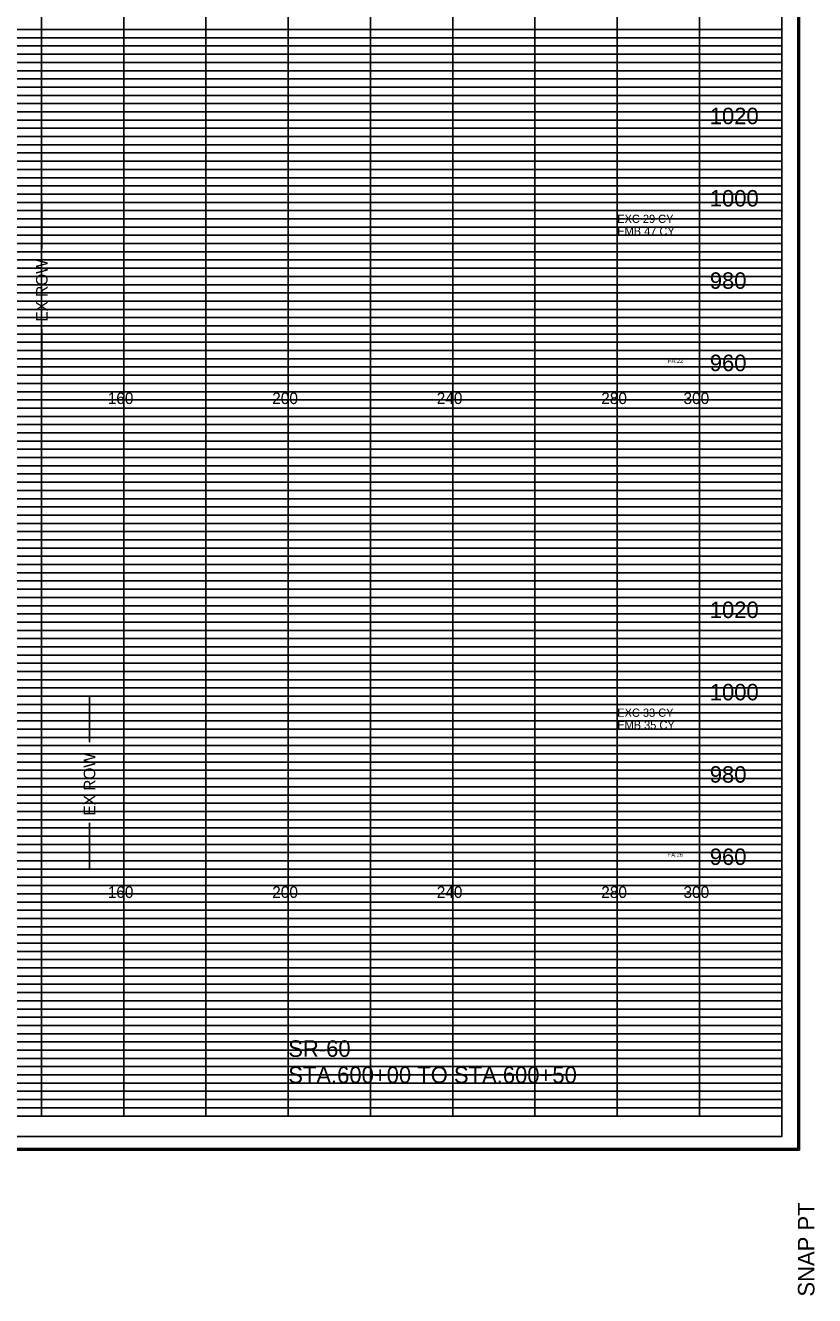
# Model space of a CAD drawing. Extents: x 2313580 to 2322968, y 282099 to 303247.
# Drawn here: x 2317337.4 to 2317529.3, y 287544 to 287852.7 of the extents above; entities that cross this region are included whole.
import ezdxf

# ---------------------------------------------------------------- set-up
doc = ezdxf.new("R2010")
doc.units = 0
for name, color, linetype in [('DESIGN - EARTHWORK - Excavation Limit Lines', 7, 'Continuous'), ('DESIGN - SHEET - Corner Text', 7, 'Continuous'), ('DESIGN - SHEET - Light Grid', 7, 'Continuous'), ('DESIGN - SHEET - Linework', 7, 'Continuous'), ('DESIGN - SHEET - Plot Shape', 7, 'Continuous'), ('DESIGN - TYPICAL - Text', 7, 'Continuous'), ('Prop_ CL text', 7, 'Continuous'), ('SURVEY - PROPERTY - ROW Lines Text', 7, 'Continuous')]:
    doc.layers.add(name, color=color, linetype=linetype)

msp = doc.modelspace()

# ---------------------------------------------------------------- linework, layer by layer
at = {"layer": 'DESIGN - SHEET - Light Grid'}
for p, q in [((2317201.28, 287851.67), (2317361.28, 287851.67)), ((2317361.28, 287851.67), (2317521.28, 287851.67)), ((2317201.28, 287849.67), (2317361.28, 287849.67)), ((2317361.28, 287849.67), (2317521.28, 287849.67)), ((2317201.28, 287845.67), (2317361.28, 287845.67)), ((2317361.28, 287845.67), (2317521.28, 287845.67)), ((2317201.28, 287843.67), (2317361.28, 287843.67)), ((2317201.28, 287841.67), (2317361.28, 287841.67)), ((2317361.28, 287843.67), (2317521.28, 287843.67)), ((2317361.28, 287841.67), (2317521.28, 287841.67)), ((2317201.28, 287839.67), (2317361.28, 287839.67)), ((2317361.28, 287839.67), (2317521.28, 287839.67)), ((2317201.28, 287837.67), (2317361.28, 287837.67)), ((2317201.28, 287835.67), (2317361.28, 287835.67)), ((2317361.28, 287837.67), (2317521.28, 287837.67)), ((2317361.28, 287835.67), (2317521.28, 287835.67)), ((2317201.28, 287833.67), (2317361.28, 287833.67)), ((2317201.28, 287831.67), (2317361.28, 287831.67)), ((2317361.28, 287833.67), (2317521.28, 287833.67)), ((2317361.28, 287831.67), (2317521.28, 287831.67)), ((2317201.28, 287829.67), (2317361.28, 287829.67)), ((2317361.28, 287829.67), (2317521.28, 287829.67)), ((2317201.28, 287825.67), (2317361.28, 287825.67)), ((2317361.28, 287825.67), (2317521.28, 287825.67)), ((2317201.28, 287823.67), (2317361.28, 287823.67)), ((2317361.28, 287823.67), (2317521.28, 287823.67)), ((2317201.28, 287821.67), (2317361.28, 287821.67)), ((2317201.28, 287819.67), (2317361.28, 287819.67)), ((2317361.28, 287821.67), (2317521.28, 287821.67)), ((2317361.28, 287819.67), (2317521.28, 287819.67)), ((2317201.28, 287817.67), (2317361.28, 287817.67)), ((2317361.28, 287817.67), (2317521.28, 287817.67)), ((2317201.28, 287815.67), (2317361.28, 287815.67)), ((2317201.28, 287813.67), (2317361.28, 287813.67)), ((2317361.28, 287815.67), (2317521.28, 287815.67)), ((2317361.28, 287813.67), (2317521.28, 287813.67)), ((2317201.28, 287811.67), (2317361.28, 287811.67)), ((2317361.28, 287811.67), (2317521.28, 287811.67)), ((2317201.28, 287809.67), (2317361.28, 287809.67)), ((2317361.28, 287809.67), (2317521.28, 287809.67)), ((2317201.28, 287805.67), (2317361.28, 287805.67)), ((2317361.28, 287805.67), (2317521.28, 287805.67)), ((2317201.28, 287803.67), (2317361.28, 287803.67)), ((2317201.28, 287801.67), (2317361.28, 287801.67)), ((2317361.28, 287803.67), (2317521.28, 287803.67)), ((2317361.28, 287801.67), (2317521.28, 287801.67)), ((2317201.28, 287799.67), (2317361.28, 287799.67)), ((2317201.28, 287797.67), (2317361.28, 287797.67)), ((2317361.28, 287799.67), (2317521.28, 287799.67)), ((2317361.28, 287797.67), (2317521.28, 287797.67)), ((2317201.28, 287795.67), (2317361.28, 287795.67)), ((2317361.28, 287795.67), (2317521.28, 287795.67)), ((2317201.28, 287793.67), (2317361.28, 287793.67)), ((2317201.28, 287791.67), (2317361.28, 287791.67)), ((2317361.28, 287793.67), (2317521.28, 287793.67)), ((2317361.28, 287791.67), (2317521.28, 287791.67)), ((2317201.28, 287789.67), (2317361.28, 287789.67)), ((2317361.28, 287789.67), (2317521.28, 287789.67)), ((2317201.28, 287785.67), (2317361.28, 287785.67)), ((2317361.28, 287785.67), (2317521.28, 287785.67)), ((2317201.28, 287783.67), (2317361.28, 287783.67)), ((2317361.28, 287783.67), (2317521.28, 287783.67)), ((2317201.28, 287781.67), (2317361.28, 287781.67)), ((2317201.28, 287779.67), (2317361.28, 287779.67)), ((2317361.28, 287781.67), (2317521.28, 287781.67)), ((2317361.28, 287779.67), (2317521.28, 287779.67)), ((2317201.28, 287777.67), (2317361.28, 287777.67)), ((2317361.28, 287777.67), (2317521.28, 287777.67)), ((2317201.28, 287775.67), (2317361.28, 287775.67)), ((2317201.28, 287773.67), (2317361.28, 287773.67)), ((2317361.28, 287775.67), (2317521.28, 287775.67)), ((2317361.28, 287773.67), (2317521.28, 287773.67)), ((2317201.28, 287771.67), (2317361.28, 287771.67)), ((2317361.28, 287771.67), (2317521.28, 287771.67)), ((2317201.28, 287769.67), (2317361.28, 287769.67)), ((2317361.28, 287769.67), (2317521.28, 287769.67)), ((2317201.28, 287765.67), (2317361.28, 287765.67)), ((2317201.28, 287763.67), (2317361.28, 287763.67)), ((2317361.28, 287765.67), (2317521.28, 287765.67)), ((2317361.28, 287763.67), (2317521.28, 287763.67)), ((2317201.28, 287761.67), (2317361.28, 287761.67)), ((2317361.28, 287761.67), (2317521.28, 287761.67)), ((2317201.28, 287759.67), (2317361.28, 287759.67)), ((2317201.28, 287757.67), (2317361.28, 287757.67)), ((2317361.28, 287759.67), (2317521.28, 287759.67)), ((2317361.28, 287757.67), (2317521.28, 287757.67)), ((2317201.28, 287755.67), (2317361.28, 287755.67)), ((2317361.28, 287755.67), (2317521.28, 287755.67)), ((2317201.28, 287753.67), (2317361.28, 287753.67)), ((2317201.28, 287751.67), (2317361.28, 287751.67)), ((2317361.28, 287753.67), (2317521.28, 287753.67)), ((2317361.28, 287751.67), (2317521.28, 287751.67)), ((2317201.28, 287749.67), (2317361.28, 287749.67)), ((2317361.28, 287749.67), (2317521.28, 287749.67)), ((2317201.28, 287745.67), (2317361.28, 287745.67)), ((2317361.28, 287745.67), (2317521.28, 287745.67)), ((2317201.28, 287743.67), (2317361.28, 287743.67)), ((2317361.28, 287743.67), (2317521.28, 287743.67)), ((2317201.28, 287741.67), (2317361.28, 287741.67)), ((2317201.28, 287739.67), (2317361.28, 287739.67)), ((2317361.28, 287741.67), (2317521.28, 287741.67)), ((2317361.28, 287739.67), (2317521.28, 287739.67)), ((2317201.28, 287737.67), (2317361.28, 287737.67)), ((2317361.28, 287737.67), (2317521.28, 287737.67)), ((2317201.28, 287735.67), (2317361.28, 287735.67)), ((2317201.28, 287733.67), (2317361.28, 287733.67)), ((2317361.28, 287735.67), (2317521.28, 287735.67)), ((2317361.28, 287733.67), (2317521.28, 287733.67)), ((2317201.28, 287731.67), (2317361.28, 287731.67)), ((2317361.28, 287731.67), (2317521.28, 287731.67)), ((2317201.28, 287729.67), (2317361.28, 287729.67)), ((2317361.28, 287729.67), (2317521.28, 287729.67)), ((2317201.28, 287725.67), (2317361.28, 287725.67)), ((2317201.28, 287723.67), (2317361.28, 287723.67)), ((2317361.28, 287725.67), (2317521.28, 287725.67)), ((2317361.28, 287723.67), (2317521.28, 287723.67)), ((2317201.28, 287721.67), (2317361.28, 287721.67)), ((2317361.28, 287721.67), (2317521.28, 287721.67)), ((2317201.28, 287719.67), (2317361.28, 287719.67)), ((2317201.28, 287717.67), (2317361.28, 287717.67)), ((2317361.28, 287719.67), (2317521.28, 287719.67)), ((2317361.28, 287717.67), (2317521.28, 287717.67)), ((2317201.28, 287715.67), (2317361.28, 287715.67)), ((2317361.28, 287715.67), (2317521.28, 287715.67)), ((2317201.28, 287713.67), (2317361.28, 287713.67)), ((2317201.28, 287711.67), (2317361.28, 287711.67)), ((2317361.28, 287713.67), (2317521.28, 287713.67)), ((2317361.28, 287711.67), (2317521.28, 287711.67)), ((2317201.28, 287709.67), (2317361.28, 287709.67)), ((2317361.28, 287709.67), (2317521.28, 287709.67)), ((2317201.28, 287705.67), (2317361.28, 287705.67)), ((2317361.28, 287705.67), (2317521.28, 287705.67)), ((2317201.28, 287703.67), (2317361.28, 287703.67)), ((2317361.28, 287703.67), (2317521.28, 287703.67)), ((2317201.28, 287701.67), (2317361.28, 287701.67)), ((2317201.28, 287699.67), (2317361.28, 287699.67)), ((2317361.28, 287701.67), (2317521.28, 287701.67)), ((2317361.28, 287699.67), (2317521.28, 287699.67)), ((2317201.28, 287697.67), (2317361.28, 287697.67)), ((2317361.28, 287697.67), (2317521.28, 287697.67)), ((2317201.28, 287695.67), (2317361.28, 287695.67)), ((2317201.28, 287693.67), (2317361.28, 287693.67)), ((2317361.28, 287695.67), (2317521.28, 287695.67)), ((2317361.28, 287693.67), (2317521.28, 287693.67)), ((2317201.28, 287691.67), (2317361.28, 287691.67)), ((2317201.28, 287689.67), (2317361.28, 287689.67)), ((2317361.28, 287691.67), (2317521.28, 287691.67)), ((2317361.28, 287689.67), (2317521.28, 287689.67)), ((2317201.28, 287685.67), (2317361.28, 287685.67)), ((2317201.28, 287683.67), (2317361.28, 287683.67)), ((2317361.28, 287685.67), (2317521.28, 287685.67)), ((2317361.28, 287683.67), (2317521.28, 287683.67)), ((2317201.28, 287681.67), (2317361.28, 287681.67)), ((2317361.28, 287681.67), (2317521.28, 287681.67)), ((2317201.28, 287679.67), (2317361.28, 287679.67)), ((2317201.28, 287677.67), (2317361.28, 287677.67)), ((2317361.28, 287679.67), (2317521.28, 287679.67)), ((2317361.28, 287677.67), (2317521.28, 287677.67)), ((2317201.28, 287675.67), (2317361.28, 287675.67)), ((2317361.28, 287675.67), (2317521.28, 287675.67)), ((2317201.28, 287673.67), (2317361.28, 287673.67)), ((2317201.28, 287671.67), (2317361.28, 287671.67)), ((2317361.28, 287673.67), (2317521.28, 287673.67)), ((2317361.28, 287671.67), (2317521.28, 287671.67)), ((2317201.28, 287669.67), (2317361.28, 287669.67)), ((2317361.28, 287669.67), (2317521.28, 287669.67)), ((2317201.28, 287665.67), (2317361.28, 287665.67)), ((2317361.28, 287665.67), (2317521.28, 287665.67)), ((2317201.28, 287663.67), (2317361.28, 287663.67)), ((2317361.28, 287663.67), (2317521.28, 287663.67)), ((2317201.28, 287661.67), (2317361.28, 287661.67)), ((2317201.28, 287659.67), (2317361.28, 287659.67)), ((2317361.28, 287661.67), (2317521.28, 287661.67)), ((2317361.28, 287659.67), (2317521.28, 287659.67)), ((2317201.28, 287657.67), (2317361.28, 287657.67)), ((2317201.28, 287655.67), (2317361.28, 287655.67)), ((2317361.28, 287657.67), (2317521.28, 287657.67)), ((2317361.28, 287655.67), (2317521.28, 287655.67)), ((2317201.28, 287653.67), (2317361.28, 287653.67)), ((2317361.28, 287653.67), (2317521.28, 287653.67)), ((2317201.28, 287651.67), (2317361.28, 287651.67)), ((2317201.28, 287649.67), (2317361.28, 287649.67)), ((2317361.28, 287651.67), (2317521.28, 287651.67)), ((2317361.28, 287649.67), (2317521.28, 287649.67)), ((2317201.28, 287645.67), (2317361.28, 287645.67)), ((2317201.28, 287643.67), (2317361.28, 287643.67)), ((2317361.28, 287645.67), (2317521.28, 287645.67)), ((2317361.28, 287643.67), (2317521.28, 287643.67)), ((2317201.28, 287641.67), (2317361.28, 287641.67)), ((2317361.28, 287641.67), (2317521.28, 287641.67)), ((2317201.28, 287639.67), (2317361.28, 287639.67)), ((2317201.28, 287637.67), (2317361.28, 287637.67)), ((2317361.28, 287639.67), (2317521.28, 287639.67)), ((2317361.28, 287637.67), (2317521.28, 287637.67)), ((2317201.28, 287635.67), (2317361.28, 287635.67)), ((2317361.28, 287635.67), (2317521.28, 287635.67)), ((2317201.28, 287633.67), (2317361.28, 287633.67)), ((2317201.28, 287631.67), (2317361.28, 287631.67)), ((2317361.28, 287633.67), (2317521.28, 287633.67)), ((2317361.28, 287631.67), (2317521.28, 287631.67)), ((2317201.28, 287629.67), (2317361.28, 287629.67)), ((2317361.28, 287629.67), (2317521.28, 287629.67)), ((2317201.28, 287625.67), (2317361.28, 287625.67)), ((2317361.28, 287625.67), (2317521.28, 287625.67)), ((2317201.28, 287623.67), (2317361.28, 287623.67)), ((2317361.28, 287623.67), (2317521.28, 287623.67)), ((2317201.28, 287621.67), (2317361.28, 287621.67)), ((2317201.28, 287619.67), (2317361.28, 287619.67)), ((2317361.28, 287621.67), (2317521.28, 287621.67)), ((2317361.28, 287619.67), (2317521.28, 287619.67)), ((2317201.28, 287617.67), (2317361.28, 287617.67)), ((2317201.28, 287615.67), (2317361.28, 287615.67)), ((2317361.28, 287617.67), (2317521.28, 287617.67)), ((2317361.28, 287615.67), (2317521.28, 287615.67)), ((2317201.28, 287613.67), (2317361.28, 287613.67)), ((2317361.28, 287613.67), (2317521.28, 287613.67)), ((2317201.28, 287611.67), (2317361.28, 287611.67)), ((2317201.28, 287609.67), (2317361.28, 287609.67)), ((2317361.28, 287611.67), (2317521.28, 287611.67)), ((2317361.28, 287609.67), (2317521.28, 287609.67)), ((2317201.28, 287605.67), (2317361.28, 287605.67)), ((2317201.28, 287603.67), (2317361.28, 287603.67)), ((2317361.28, 287605.67), (2317521.28, 287605.67)), ((2317361.28, 287603.67), (2317521.28, 287603.67)), ((2317201.28, 287601.67), (2317361.28, 287601.67)), ((2317361.28, 287601.67), (2317521.28, 287601.67)), ((2317201.28, 287599.67), (2317361.28, 287599.67)), ((2317201.28, 287597.67), (2317361.28, 287597.67)), ((2317361.28, 287599.67), (2317521.28, 287599.67)), ((2317361.28, 287597.67), (2317521.28, 287597.67)), ((2317201.28, 287595.67), (2317361.28, 287595.67)), ((2317361.28, 287595.67), (2317521.28, 287595.67)), ((2317201.28, 287593.67), (2317361.28, 287593.67)), ((2317201.28, 287591.67), (2317361.28, 287591.67)), ((2317361.28, 287593.67), (2317521.28, 287593.67)), ((2317361.28, 287591.67), (2317521.28, 287591.67)), ((2317201.28, 287589.67), (2317361.28, 287589.67)), ((2317361.28, 287589.67), (2317521.28, 287589.67))]:
    msp.add_line(p, q, dxfattribs=at)
at = {"layer": 'DESIGN - SHEET - Linework'}
for p, q in [((2317525.62, 288015.95), (2317525.62, 287579.39)), ((2317341.28, 287587.67), (2317341.28, 288007.67)), ((2317361.28, 287587.67), (2317361.28, 288007.67)), ((2317381.28, 287587.67), (2317381.28, 288007.67)), ((2317401.28, 287587.67), (2317401.28, 288007.67)), ((2317421.28, 287587.67), (2317421.28, 288007.67)), ((2317441.28, 287587.67), (2317441.28, 287987.67)), ((2317461.28, 287587.67), (2317461.28, 287987.67)), ((2317481.28, 287587.67), (2317481.28, 287987.67)), ((2317501.28, 287587.67), (2317501.28, 287987.67)), ((2316881.28, 287847.67), (2317521.28, 287847.67)), ((2316881.28, 287827.67), (2317521.28, 287827.67)), ((2316881.28, 287807.67), (2317521.28, 287807.67)), ((2316881.28, 287787.67), (2317521.28, 287787.67)), ((2316881.28, 287767.67), (2317521.28, 287767.67)), ((2316881.28, 287747.67), (2317521.28, 287747.67)), ((2316881.28, 287727.67), (2317521.28, 287727.67)), ((2316881.28, 287707.67), (2317521.28, 287707.67)), ((2316881.28, 287687.67), (2317521.28, 287687.67)), ((2316881.28, 287667.67), (2317521.28, 287667.67)), ((2316881.28, 287647.67), (2317521.28, 287647.67)), ((2316881.28, 287627.67), (2317521.28, 287627.67)), ((2316881.28, 287607.67), (2317521.28, 287607.67)), ((2316844.82, 287579.39), (2317525.62, 287579.39))]:
    msp.add_line(p, q, dxfattribs=at)
msp.add_lwpolyline([(2316881.28, 288007.67), (2316881.28, 287587.67), (2317521.28, 287587.67), (2317521.28, 288007.67), (2316881.28, 288007.67)], dxfattribs=at)
at = {"layer": 'DESIGN - SHEET - Plot Shape'}
for points in [[(2316845.22, 288015.55), (2317525.22, 288015.55), (2317525.22, 287579.79), (2316845.22, 287579.79)], [(2316864.28, 288007.67), (2317521.28, 288007.67), (2317521.28, 287582.67), (2316864.28, 287582.67)]]:
    msp.add_lwpolyline(points, close=True, dxfattribs=at)
at = {"layer": 'SURVEY - PROPERTY - ROW Lines Text'}
for p, q in [((2317341.35, 287809.67), (2317341.35, 287798.47)), ((2317341.35, 287767.67), (2317341.35, 287778.87)), ((2317352.95, 287689.67), (2317352.95, 287678.47)), ((2317352.95, 287647.67), (2317352.95, 287658.87))]:
    msp.add_line(p, q, dxfattribs=at)

# ---------------------------------------------------------------- texts
at = {"layer": 'DESIGN - EARTHWORK - Excavation Limit Lines'}
for s, p in [('EXC 29 CY', (2317481.28, 287804.67)), ('EMB 47 CY', (2317481.28, 287801.67)), ('EXC 33 CY', (2317481.28, 287684.67)), ('EMB 35 CY', (2317481.28, 287681.67))]:
    msp.add_text(s, height=2, dxfattribs=at).set_placement(p)
at = {"layer": 'DESIGN - SHEET - Corner Text'}
msp.add_text('SNAP PT  ', height=4, rotation=90, dxfattribs=at).set_placement((2317529.22, 287543.79))
at = {"layer": 'DESIGN - TYPICAL - Text'}
for s, height, p in [('1020', 4, (2317503.78, 287828.67)), ('1000', 4, (2317503.78, 287808.67)), ('980', 4, (2317503.78, 287788.67)), ('960', 4, (2317503.78, 287768.67)), ('160', 2.8, (2317357.39, 287760.67)), ('200', 2.8, (2317397.39, 287760.67)), ('240', 2.8, (2317437.39, 287760.67)), ('280', 2.8, (2317477.39, 287760.67)), ('300', 2.8, (2317497.39, 287760.67)), ('1020', 4, (2317503.78, 287708.67)), ('1000', 4, (2317503.78, 287688.67)), ('980', 4, (2317503.78, 287668.67)), ('960', 4, (2317503.78, 287648.67)), ('160', 2.8, (2317357.39, 287640.67)), ('200', 2.8, (2317397.39, 287640.67)), ('240', 2.8, (2317437.39, 287640.67)), ('280', 2.8, (2317477.39, 287640.67)), ('300', 2.8, (2317497.39, 287640.67)), ('SR-60', 4, (2317401.28, 287602.05)), ('STA.600+00 TO STA.600+50', 4, (2317401.28, 287595.67))]:
    msp.add_text(s, height=height, dxfattribs=at).set_placement(p)
at = {"layer": 'Prop_ CL text'}
for s, p in [('FA:22', (2317493.63, 287770.67)), ('FA:26', (2317493.58, 287650.67))]:
    msp.add_text(s, height=1, dxfattribs=at).set_placement(p)
at = {"layer": 'SURVEY - PROPERTY - ROW Lines Text'}
for p in [(2317342.75, 287780.67), (2317354.35, 287660.67)]:
    msp.add_text('EX ROW', height=2.8, rotation=90, dxfattribs=at).set_placement(p)

doc.saveas('drawing.dxf')
